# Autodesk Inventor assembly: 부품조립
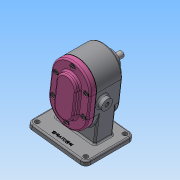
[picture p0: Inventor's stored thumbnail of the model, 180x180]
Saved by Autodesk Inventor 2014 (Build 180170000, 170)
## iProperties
Created: 2020-09
Part Number: 부품조립
Document SubType Name: Assembly
Designer: NET
Author: NET
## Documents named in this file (11)
- C:\Users\NET\Desktop\700906V1019\부품조립.iam
- C:\Users\NET\Desktop\700906V1019\부품.ipt
- C:\Users\NET\Desktop\700906V1019\베어링부시.ipt
- C:\Users\NET\Desktop\700906V1019\메인축.ipt
- C:\Users\NET\Desktop\700906V1019\서브축.ipt
- C:\Users\NET\Desktop\700906V1019\스퍼기어.ipt
- C:\Users\NET\Desktop\700906V1019\키 6 x 6 x 18.ipt
- C:\Users\NET\Desktop\700906V1019\커버.ipt
- C:\Users\NET\Desktop\700906V1019\개스킷.ipt
- C:\Users\NET\Desktop\700906V1019\볼트 M5.ipt
- C:\Users\NET\Desktop\700906V1019\오일 실 16 28 7.ipt
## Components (1 placed, 1 different names)
1. 개스킷:1
